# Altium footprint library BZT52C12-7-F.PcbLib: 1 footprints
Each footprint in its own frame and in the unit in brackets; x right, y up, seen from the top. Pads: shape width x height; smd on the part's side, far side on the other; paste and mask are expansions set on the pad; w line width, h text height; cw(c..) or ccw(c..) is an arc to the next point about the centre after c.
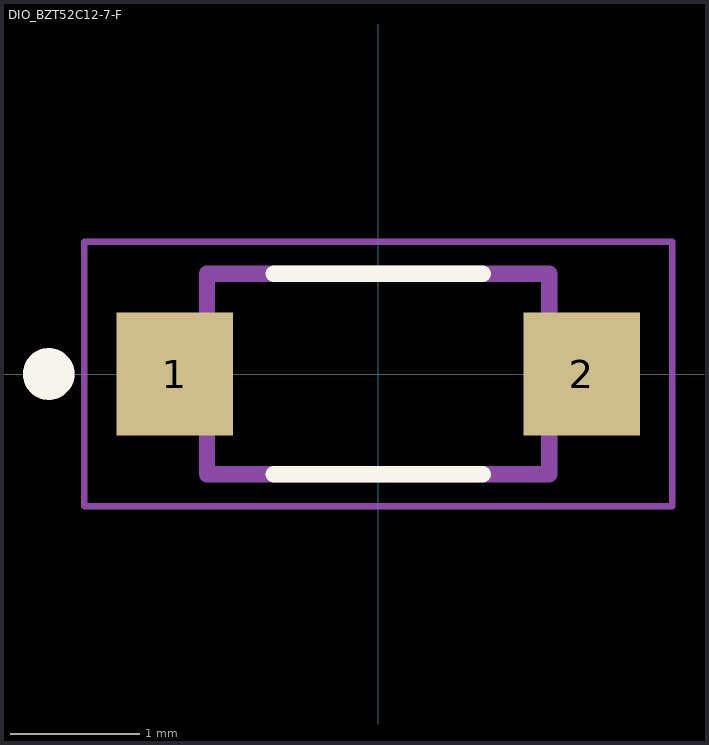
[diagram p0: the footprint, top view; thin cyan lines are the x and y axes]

## DIO_BZT52C12-7-F [mm]
height 1.45
pads (2):
  rect 0.9x0.95 smd paste+0 mask+0.102: 1(-1.575,0) 2(1.575,0)
Top Overlay:
  circle w0.2: c-2.55,0 r0.1
  lines w0.127: -0.81,-0.775 0.81,-0.775 ; -0.81,0.775 0.81,0.775
Assembly Top:
  circle w0.2: c-2.55,0 r0.1
  lines w0.127: -1.325,-0.775 -1.325,0.775 1.325,0.775 1.325,-0.775 -1.325,-0.775
Courtyard Top:
  lines w0.05: -2.275,-1.025 -2.275,1.025 2.275,1.025 2.275,-1.025 -2.275,-1.025
3D body "step_temp.STEP": height 1.35, standoff 0, extent -1.85,-0.775 1.85,0.775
